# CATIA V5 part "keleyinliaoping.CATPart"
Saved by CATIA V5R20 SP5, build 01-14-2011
Part number: 可乐饮料瓶
Material "Sunset 2"
Bounding box of the stored display mesh (mm): x -25 to 25.5, y -25 to 25, z 0 to 110
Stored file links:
  E:\180522127 徐丽维\keleyinliaopingtwo.CATPart
  C:\Program Files\Dassault Systemes\B20\intel_a\startup\materials\Catalog.CATMaterial
  C:\Program Files\Dassault Systemes\B20\intel_a\startup\materials\black_env_512x512.jpg
  C:\Program Files\Dassault Systemes\B20\intel_a\startup\materials\fence_3.jpg
  C:\Program Files\Dassault Systemes\B20\intel_a\startup\materials\fence_2.jpg
  C:\Program Files\Dassault Systemes\B20\intel_a\startup\materials\pinetree.jpg
  C:\Program Files\Dassault Systemes\B20\intel_a\startup\materials\yellow_env_512x512.jpg
  C:\Program Files\Dassault Systemes\B20\intel_a\startup\materials\DS_star.jpg
  C:\Program Files\Dassault Systemes\B20\intel_a\startup\materials\raw_polystyren.jpg
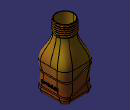
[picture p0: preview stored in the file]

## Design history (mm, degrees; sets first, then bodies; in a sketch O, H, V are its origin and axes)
Set1, material "无"
  Sketch1 on face of Pad1 from Sketch3.L2, origin (0, -25, 0), H (1, 0, 0), V (0, 0, 1)
    spline S1 through (-36.6643, 10.6384) (-12.6372, 20.3412) (12.3023, 12.4577) (37.2418, 22.4637)
  Extrude1: Element1 Sketch1, Lim1 52, Lim2 0
  MultiSel1: CommonCtxFeats ({extract ExtractElem face of Pad1 from Sketch3.L2}; {extract ExtractElem face of Fillet1}; {extract ExtractElem face of Pad1 from Sketch3.L3}; {extract ExtractElem face of Fillet1}; {extract ExtractElem face of Pad1 from Sketch3.L4}; {extract ExtractElem face of Fillet1}; {extract ExtractElem face of Pad1 from Sketch3.L1}; {extract ExtractElem face of Fillet1})
  Sketch2 on face of Pad1 from Sketch3.L4, origin (0, 25, 0), H (-1, 0, 0), V (0, 0, 1)
    spline S1 through (-35.2027, 44.7232) (-14.293, 33.6723) (16.9455, 44.7232) (38.1071, 36.6862)
  Extrude2: Element1 Sketch2, Lim1 52, Lim2 0
  MultiSel2: CommonCtxFeats ({extract ExtractElem face of Pad1 from Sketch3.L4}; {extract ExtractElem face of Fillet1}; {extract ExtractElem face of Pad1 from Sketch3.L1}; {extract ExtractElem face of Fillet1}; {extract ExtractElem face of Pad1 from Sketch3.L2}; {extract ExtractElem face of Fillet1}; {extract ExtractElem face of Pad1 from Sketch3.L3}; {extract ExtractElem face of Fillet1})
  Join1: Elements ({intersect ToIntersect1 {extract ExtractElem face of Pad1 from Sketch3.L2}, ToIntersect2 Extrude1}; {intersect ToIntersect1 {extract ExtractElem face of Fillet1}, ToIntersect2 Extrude1}; {intersect ToIntersect1 {extract ExtractElem face of Pad1 from Sketch3.L3}, ToIntersect2 Extrude1}; {intersect ToIntersect1 {extract ExtractElem face of Fillet1}, ToIntersect2 Extrude1}; {intersect ToIntersect1 {extract ExtractElem face of Pad1 from Sketch3.L4}, ToIntersect2 Extrude1}; {intersect ToIntersect1 {extract ExtractElem face of Fillet1}, ToIntersect2 Extrude1}; {intersect ToIntersect1 {extract ExtractElem face of Pad1 from Sketch3.L1}, ToIntersect2 Extrude1}; {intersect ToIntersect1 {extract ExtractElem face of Fillet1}, ToIntersect2 Extrude1})
  Join2: Elements ({intersect ToIntersect1 {extract ExtractElem face of Pad1 from Sketch3.L4}, ToIntersect2 Extrude2}; {intersect ToIntersect1 {extract ExtractElem face of Fillet1}, ToIntersect2 Extrude2}; {intersect ToIntersect1 {extract ExtractElem face of Pad1 from Sketch3.L1}, ToIntersect2 Extrude2}; {intersect ToIntersect1 {extract ExtractElem face of Fillet1}, ToIntersect2 Extrude2}; {intersect ToIntersect1 {extract ExtractElem face of Pad1 from Sketch3.L2}, ToIntersect2 Extrude2}; {intersect ToIntersect1 {extract ExtractElem face of Fillet1}, ToIntersect2 Extrude2}; {intersect ToIntersect1 {extract ExtractElem face of Pad1 from Sketch3.L3}, ToIntersect2 Extrude2}; {intersect ToIntersect1 {extract ExtractElem face of Fillet1}, ToIntersect2 Extrude2})
  Plane1: type Normal, Curve Join2, RefPoint vertex [face of MultiSel2 | face of MultiSel2]
  Circle1: type CtrRad, Start 0, End 180, Center vertex [face of MultiSel2 | face of MultiSel2], Support Plane1, Radius 1, FirstDirection (-1, 0, 0)
Body1 (main body)
  Sketch3 on xy-plane, origin (0, 0, 0), H (1, 0, 0), V (0, 1, 0)
    line L1 (25, 25) -> (25, -25)
    line L2 (25, -25) -> (-25, -25)
    line L3 (-25, -25) -> (-25, 25)
    line L4 (-25, 25) -> (25, 25)
    length L1 = 50
    length L4 = 50
    vertical: L1 V, L3 V
    horizontal: L2 H, L4 H
    equidistance: L1 L3 O, L2 L4 O
  Pad1: profile Sketch3, direction (0, 0, 1), length 50
  Fillet1: on edge [face of Pad1 from Sketch3.L1 | face of Pad1 from Sketch3.L2]; edge [face of Pad1 from Sketch3.L2 | face of Pad1 from Sketch3.L3]; edge [face of Pad1 from Sketch3.L3 | face of Pad1 from Sketch3.L4]; edge [face of Pad1 from Sketch3.L4 | face of Pad1 from Sketch3.L1]
  Fillet2: radius 8, on start face of Pad1
  Plane2: type Offset, RefPlane end face of Pad1, Offset 40, reversed
  Sketch4 on Plane2, origin (0, 0, 90), H (1, 0, 0), V (0, -1, 0)
    circle A1 centre (0, 0) radius 15
    radius A1 = 15
  Pad2: profile Sketch4, direction (0, 0, 1), length 20
  Sketch5 on end face of Pad1, origin (0, 0, 50), H (1, 0, 0), V (0, 1, 0)
    point P1 (25, 0)
    distance P1 V = 25
    coincidence: P1 H
  Sketch6 on start face of Pad2, origin (0, 0, 90), H (1, 0, 0), V (0, -1, 0)
    point P1 (15, 0)
    distance P1 V = 15
    coincidence: P1 H
  Loft1: solid, Sections ({boundary Boundary {extract ExtractElem end face of Pad1}}; {boundary Boundary {extract ExtractElem start face of Pad2}}), StartFace end face of Pad1, EndFace start face of Pad2
  Slot1: profile Circle1, centre curve Join2
  Plane3: type Normal, Curve Join1, RefPoint vertex [face of MultiSel1 | face of MultiSel1]
  Circle2: type CtrRad, Start 0, End 180, Center vertex [face of MultiSel1 | face of MultiSel1], Support Plane3, Radius 1, FirstDirection (-1, 0, 0)
  Slot2: profile Circle2, centre curve Join1
  Shell1: ExtOffset 0, Face end face of Pad2, IntOffset 1
  Point1: type OnSurface, Support face of Pad2 from Sketch4.A1, RefPoint Sketch6, Length 2, Direction (0, 0, 1)
  Helix1: Direction Z axis, RefPoint Point1, Pitch 3, Height 16, TaperAngle 0
  Point2: type OnCurve, Support Helix1, RefPoint Point1, Length 5
  Line1: type PtDir, RefPoint Point1, Direction (1, 0, 0), Start 0, End 5
  Connect1: Curve1 Line1, Point1 vertex of Line1, Tension1 1, Curve2 Helix1, Point2 Point2, Tension2 1
  Point3: type OnCurve, Support Connect1, RefPoint vertex of Helix1, Length -5
  Line2: type PtDir, RefPoint vertex of Helix1, Direction (0, 1, 0), Start 0, End 5
  Connect2: Curve1 Line2, Point1 vertex of Line2, Tension1 1, Curve2 Connect1, Point2 Point3, Tension2 1
  Plane4: type Normal, Curve Connect2, RefPoint vertex of Connect2
  Circle3: type CtrRad, Start 0, End 180, Radius 1, Center vertex of Connect2, Support Plane4, FirstDirection (-1, 0, 0)
  Rib1: profile Circle3, centre curve Connect2
  Body2
    Sketch7 on Plane2, origin (0, 0, 90), H (1, 0, 0), V (0, -1, 0)
      circle A1 centre (0, 0) radius 14
      radius A1 = 14
    Pad3: profile Sketch7, direction (0, 0, 1), length 20
  Remove1: tool Body2
Body3
  Sketch8 on face of Pad1 from Sketch3.L1, origin (25, 0, 0), H (0, 1, 0), V (0, 0, 1)
    polyline C1
    polyline C2
    polyline C3
    polyline C4
    polyline C5
    polyline C6
    polyline C7
    polyline C8
    polyline C9
    polyline C10
    polyline C11
  Pad4: profile Sketch8, direction (1, 0, 0), length 0.5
